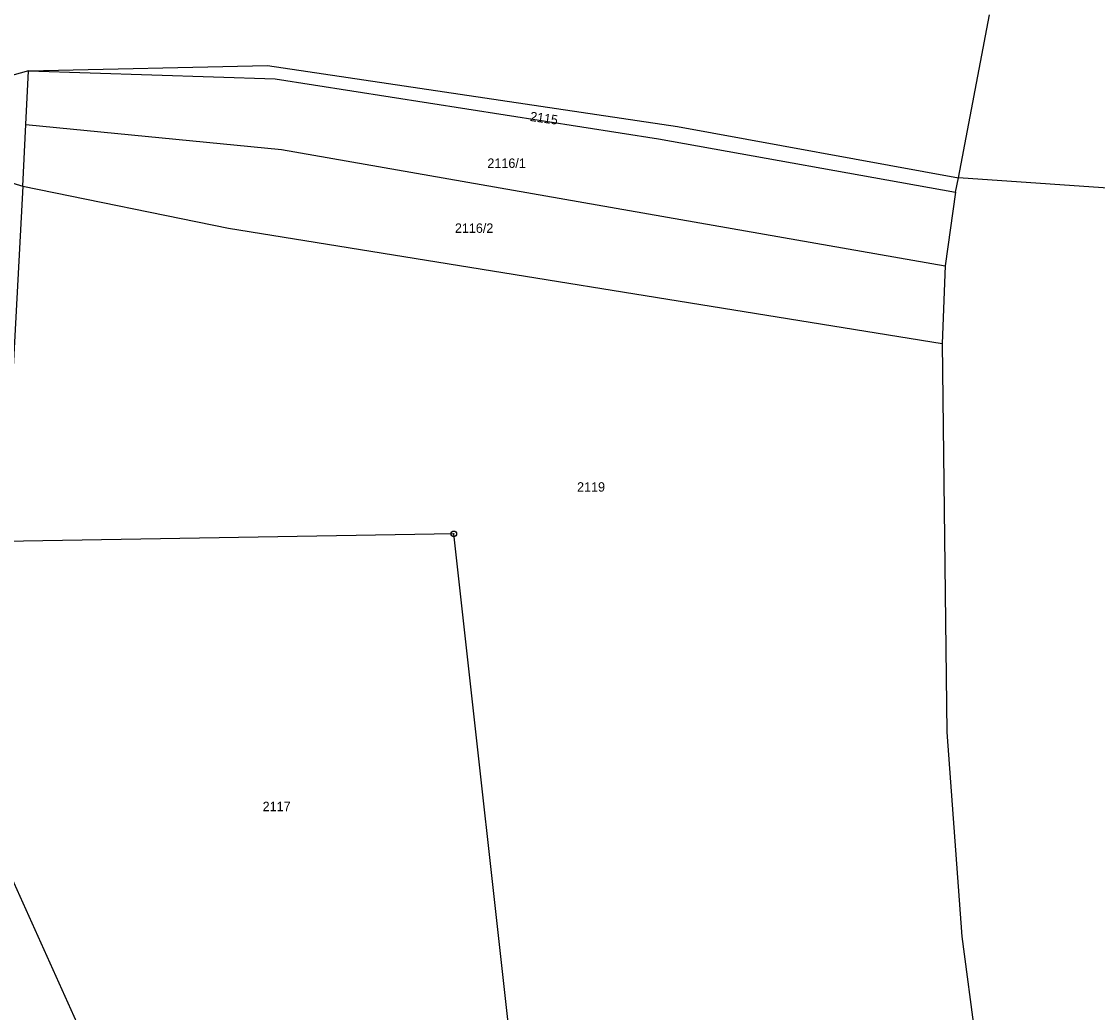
# Model space of a CAD drawing. Extents: x -725728 to -720881, y -1068679 to -1063504.
# Drawn here: x -722064.8 to -721870.1, y -1066476.7 to -1066297.3 of the extents above; entities that cross this region are included whole.
import ezdxf

# ---------------------------------------------------------------- set-up
doc = ezdxf.new("R2010")
doc.units = 0
for name, color, linetype in [('Hranice parcel', 7, 'Continuous'), ('Parcelní čísla', 7, 'Continuous'), ('Značky bodu BP', 7, 'Continuous')]:
    doc.layers.add(name, color=color, linetype=linetype)

msp = doc.modelspace()

# ---------------------------------------------------------------- linework, layer by layer
at = {"layer": 'Hranice parcel'}
for p, q in [((-721895.27, -1066325.58), (-721889.66, -1066296.08)), ((-722063.58, -1066306.2), (-722071.05, -1066308.3)), ((-722064.06, -1066315.93), (-722063.58, -1066306.2)), ((-722064.62, -1066327.13), (-722064.06, -1066315.93)), ((-722072.42, -1066324.72), (-722064.62, -1066327.13)), ((-721895.83, -1066328.2), (-721895.27, -1066325.58)), ((-722064.62, -1066327.13), (-722068.07, -1066391.45)), ((-721895.83, -1066328.2), (-721897.7, -1066341.53)), ((-721897.7, -1066341.53), (-721898.26, -1066355.61))]:
    msp.add_line(p, q, dxfattribs=at)
for points in [[(-722063.58, -1066306.2), (-722020.32, -1066305.25), (-721946.13, -1066316.3), (-721895.27, -1066325.58)], [(-722063.58, -1066306.2), (-722018.96, -1066307.65), (-721949.59, -1066318.55), (-721895.83, -1066328.2)], [(-722064.06, -1066315.93), (-722017.81, -1066320.45), (-721897.7, -1066341.53)], [(-721781.47, -1066332.92), (-721804.2, -1066332.11), (-721822.37, -1066330.58), (-721843.77, -1066329.17), (-721895.27, -1066325.58)], [(-722064.62, -1066327.13), (-722027.39, -1066334.7), (-721898.26, -1066355.61)], [(-721898.26, -1066355.61), (-721897.38, -1066425.95), (-721894.71, -1066462.94), (-721892.2, -1066481.66)], [(-721975, -1066494.79), (-721986.62, -1066390.04), (-722068.07, -1066391.45)], [(-722068.07, -1066391.45), (-722071.36, -1066432.18), (-722070.65, -1066443.54), (-722053.23, -1066482.18), (-722051.04, -1066491.64)]]:
    msp.add_lwpolyline(points, dxfattribs=at)
at = {"layer": 'Značky bodu BP'}
for radius in [0.5, 0.0303]:
    msp.add_circle((-721986.62, -1066390.04), radius, dxfattribs=at)

# ---------------------------------------------------------------- texts
at = {"layer": 'Parcelní čísla'}
msp.add_text('2115', height=1.7, rotation=352, dxfattribs=at).set_placement((-721972.91, -1066315.28))
for s, p in [('2116/1', (-721980.54, -1066323.79)), ('2116/2', (-721986.42, -1066335.55)), ('2119', (-721964.31, -1066382.4)), ('2117', (-722021.21, -1066440.25))]:
    msp.add_text(s, height=1.7, dxfattribs=at).set_placement(p)

doc.saveas('drawing.dxf')
